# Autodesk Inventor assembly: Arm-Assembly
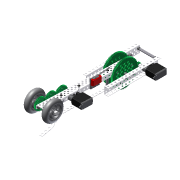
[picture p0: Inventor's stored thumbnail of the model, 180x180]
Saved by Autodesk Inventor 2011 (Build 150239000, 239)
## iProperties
Created: 2007-12
Part Number: Arm-Assembly
Document SubType Name: Assembly
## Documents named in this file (26)
- C:\Data Folder\VEX 2011\Inventor Datasets\Unit 6\Arm-Assembly.iam
- C:\Data Folder\VEX 2011\Inventor Datasets\Unit 6\Components\SCREW-832-0250.ipt
- C:\Data Folder\VEX 2011\Inventor Datasets\Unit 6\Components\BEARING-FLAT.ipt
- C:\Data Folder\VEX 2011\Inventor Datasets\Unit 6\Components\SCREW-832-0375.ipt
- C:\Data Folder\VEX 2011\Inventor Datasets\Unit 6\Components\NUT-832-KEPS.iam
- C:\Data Folder\VEX 2011\Inventor Datasets\Unit 6\Components\SPACER-THICK.ipt
- C:\Data Folder\VEX 2011\Inventor Datasets\Unit 6\Components\SPACER-THIN.ipt
- C:\Data Folder\VEX 2011\Inventor Datasets\Unit 6\Components\SHAFT-COLLAR.iam
- C:\Data Folder\VEX 2011\Inventor Datasets\Unit 6\Components\SHAFT-3000.ipt
- C:\Data Folder\VEX 2011\Inventor Datasets\Unit 6\Components\VEX-36-TOOTH-GEAR.ipt
- C:\Data Folder\VEX 2011\Inventor Datasets\Unit 6\Components\VEX-12-TOOTH-GEAR.ipt
- C:\Data Folder\VEX 2011\Inventor Datasets\Unit 6\Components\VEX-84-TOOTH-GEAR.ipt
- C:\Data Folder\VEX 2011\Inventor Datasets\Unit 6\Components\VL-CHAN-121-25 RevA.ipt
- C:\Data Folder\VEX 2011\Inventor Datasets\Unit 6\Components\SCREW-832-0500.ipt
- C:\Data Folder\VEX 2011\Inventor Datasets\Unit 6\Components\BEARING-RIVET.ipt
- C:\Data Folder\VEX 2011\Inventor Datasets\Unit 6\Components\VEX-MOTOR.iam
- C:\Data Folder\VEX 2011\Inventor Datasets\Unit 6\Components\SCREW-632-0250.ipt
- C:\Data Folder\VEX 2011\Inventor Datasets\Unit 6\Components\SHAFT-2000.ipt
- C:\Data Folder\VEX 2011\Inventor Datasets\Unit 6\Components\LIMIT-SWITCH.iam
- C:\Data Folder\VEX 2011\Inventor Datasets\Unit 6\Components\BEAM-1000.ipt
- C:\Data Folder\VEX 2011\Inventor Datasets\Unit 6\Components\BEAM-2000.ipt
- C:\Data Folder\VEX 2011\Inventor Datasets\Unit 6\Components\VL-CHAN-121-15 RevA.ipt
- C:\Data Folder\VEX 2011\Inventor Datasets\Unit 6\Components\SHAFT-4000.ipt
- C:\Data Folder\VEX 2011\Inventor Datasets\Unit 6\Components\VEX-SMALL-WHEEL.iam
- C:\Data Folder\VEX 2011\Inventor Datasets\Unit 6\Components\VL-BAR-25-bent.ipt
- C:\Data Folder\VEX 2011\Inventor Datasets\Unit 6\Components\SCREW-832-0750.ipt
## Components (92 placed, 25 different names)
1. SPACER-THICK:1 — Mate:159, Mate:161, Mate:162
2. SPACER-THIN:1 — Mate:126, Mate:128
3. VEX-12-TOOTH-GEAR:1 — Mate:163, Mate:164, Angle:7, Mate:279, Rotation:4, Mate:310, Mate:311
4. SCREW-832-0250:5 — Mate:114, Mate:116, Mate:117
5. BEARING-FLAT:3 — Mate:221, Mate:222, Mate:223
6. SPACER-THIN:3 — Mate:123, Mate:132
7. VL-CHAN-121-25 RevA:1 — Mate:105, Mate:106, Mate:107, Mate:108, Mate:110, Angle:1, Mate:111, Mate:112, Mate:201, Mate:210, Mate:211, Mate:212, Flush:7, Mate:214, Flush:8, Mate:215, Mate:216, Mate:217, Mate:218, Mate:219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
8. BEARING-FLAT:8 — Mate:231, Mate:232, Mate:233
9. SHAFT-COLLAR:3 [sub-assembly] — Mate:265, Mate:266
10. BEARING-FLAT:9 — Mate:149, Mate:150, Mate:151, Mate:167
11. BEARING-RIVET:1 — Mate:193, Flush:6, Mate:195
12. BEARING-RIVET:2 — Mate:192, Flush:5, Mate:194
13. BEARING-FLAT:10 — Mate:194, Mate:195, Mate:196, Mate:206
14. BEARING-FLAT:11 — Mate:146, Mate:147, Mate:148, Mate:153
15. VEX-MOTOR:1 [sub-assembly] — Mate:138, Mate:139, Mate:140, Mate:141
16. BEARING-FLAT:12 — Mate:210, Mate:211, Mate:212, Mate:213
17. SCREW-632-0250:1 — Mate:134, Mate:136, Mate:139
18. BEARING-FLAT:13 — Mate:226, Mate:227, Mate:228
19. VEX-12-TOOTH-GEAR:2 — Mate:154, Mate:155, Mate:156, Mate:158, Angle:6
20. VEX-36-TOOTH-GEAR:1 — Mate:256, Mate:257, Mate:264, Angle:19, Angle:23, Angle:24
21. VEX-36-TOOTH-GEAR:2 — Mate:259, Mate:260, Angle:18, Mate:266, Angle:23
22. VEX-36-TOOTH-GEAR:3 — Mate:240, Mate:241, Mate:248, Angle:24
23. VEX-84-TOOTH-GEAR:1 — Mate:168, Angle:10, Mate:176, Mate:177, Mate:178, Mate:179, Mate:182, Mate:183, Mate:201, Mate:287, Mate:288, Mate:290, Insert:1, Insert:2, Mate:309
24. VEX-84-TOOTH-GEAR:2 — Mate:185, Mate:186, Mate:188, Mate:207, Mate:283, Mate:284, Rotation:4, Mate:289, Mate:305
25. BEARING-RIVET:4 — Mate:142, Flush:1, Mate:146
26. SCREW-832-0250:16
27. BEARING-RIVET:5 — Mate:235, Flush:15
28. SCREW-832-0250:17 — Mate:107, Mate:108, Mate:109
29. BEARING-RIVET:7 — Mate:144, Flush:3, Mate:149
30. NUT-832-KEPS:8 [sub-assembly] — Mate:281, Mate:282
31. NUT-832-KEPS:9 [sub-assembly] — Mate:293, Mate:294
32. NUT-832-KEPS:10 [sub-assembly] — Mate:291, Mate:292
33. SCREW-832-0375:6 — Insert:2, Mate:293
34. SCREW-832-0375:7 — Mate:290, Insert:1, Mate:291
35. SHAFT-2000:4 — Mate:258, Mate:259, Angle:17, Mate:261, Mate:262, Angle:18, Mate:265
36. SHAFT-3000:4 — Mate:165, Mate:166, Mate:168, Angle:10, Mate:188, Mate:203, Mate:205, Flush:19, Angle:27
37. SHAFT-3000:5 — Mate:120, Mate:121, Drive this constraint, Mate:141, Mate:152, Mate:154, Mate:155, Mate:157, Mate:159, Mate:160, Mate:163, Angle:6, Angle:7, Angle:25, Angle:27
38. SHAFT-4000:1 — Mate:220, Mate:242, Angle:14, Mate:243, Angle:15, Mate:245, Angle:16, Mate:247, Mate:249, Mate:251, Flush:16
39. SHAFT-COLLAR:6 [sub-assembly] — Mate:263, Mate:264, Angle:20, Flush:17
40. SHAFT-COLLAR:9 [sub-assembly] — Mate:245, Mate:246, Angle:16, Flush:16
41. SHAFT-COLLAR:10 [sub-assembly] — Mate:251, Mate:252
42. SHAFT-2000:3 — Mate:225, Mate:256, Mate:263, Angle:19, Angle:20, Flush:17
43. SHAFT-COLLAR:11 [sub-assembly] — Mate:166, Mate:167, Angle:9, Mate:309
44. NUT-832-KEPS:13 [sub-assembly] — Mate:295, Mate:296
45. BEARING-RIVET:8 — Mate:267, Flush:18
46. BEAM-2000:1 — Mate:299, Mate:300, Mate:301, Mate:303
47. BEARING-RIVET:9 — Flush:11, Mate:224
48. SCREW-832-0250:24 — Mate:301, Mate:302
49. SCREW-832-0500:3 — Mate:274, Mate:276, Mate:298
50. SCREW-832-0500:4 — Mate:269, Angle:22, Mate:297
51. VL-CHAN-121-15 RevA:1 — Mate:121, Mate:122, Mate:123, Mate:132, Mate:142, Mate:143, Mate:144, Mate:145, Flush:1, Flush:2, Flush:3, Flush:4, Mate:148, Mate:151, Mate:165, Angle:9, Angle:11, Angle:12, Flush:19
52. BEARING-RIVET:11 — Mate:143, Flush:2, Mate:147
53. BEARING-RIVET:12 — Mate:145, Flush:4, Mate:150
54. BEARING-FLAT:15 — Mate:215, Mate:216, Mate:217
55. BEARING-RIVET:13 — Mate:213, Flush:7
56. BEARING-RIVET:14 — Mate:214, Flush:8
57. BEARING-RIVET:15 — Mate:229, Flush:12
58. BEARING-RIVET:16 — Mate:219, Flush:10
59. BEARING-RIVET:17 — Mate:230, Flush:13
60. BEARING-RIVET:18 — Mate:234, Flush:14
61. SHAFT-COLLAR:19 [sub-assembly] — Mate:278, Mate:279, Angle:26, Mate:311
62. SCREW-832-0250:38 — Mate:176, Mate:178, Mate:180
63. SCREW-832-0250:39 — Mate:177, Mate:179, Mate:181
64. BEAM-1000:5 — Mate:180, Mate:182, Angle:12
65. BEAM-1000:6 — Mate:181, Mate:183, Angle:11
66. SPACER-THIN:5 — Mate:236, Mate:237, Mate:244
67. SPACER-THIN:6 — Mate:247, Mate:248, Mate:250
68. SPACER-THIN:7 — Mate:160, Mate:162, Mate:164, Mate:310
69. SPACER-THIN:10 — Mate:152, Mate:153, Mate:156
70. LIMIT-SWITCH:2 [sub-assembly] — Angle:28, Mate:285, Mate:286, Mate:297, Mate:298
71. BEAM-2000:2 — Mate:109, Mate:110, Angle:1, Mate:117, Mate:119
72. VEX-MOTOR:3 [sub-assembly] — Mate:253, Mate:254, Mate:255, Angle:17, Mate:261, Mate:262
73. BEAM-2000:3 — Mate:111, Mate:112, Mate:118
74. SCREW-832-0250:41 — Mate:113, Mate:115, Mate:118
75. NUT-832-KEPS:26 [sub-assembly] — Mate:270, Mate:272, Angle:21
76. BEARING-RIVET:21 — Mate:218, Flush:9
77. SCREW-832-0375:12 — Mate:283, Mate:284, Mate:295
78. VEX-SMALL-WHEEL:1 [sub-assembly] — Mate:242, Angle:14, Mate:249, Mate:250, Mate:252
79. VEX-SMALL-WHEEL:2 [sub-assembly] — Mate:243, Angle:15, Mate:244, Mate:246
80. VL-BAR-25-bent:1 — Mate:113, Mate:114, Mate:115, Mate:116, Mate:119, Mate:304
81. SCREW-632-0250:7 — Mate:135, Mate:137, Mate:138
82. SCREW-832-0375:13 — Mate:185, Mate:186, Mate:280, Mate:281
83. SCREW-832-0250:43 — Mate:303, Mate:304
84. BEAM-2000:4 — Mate:208, Mate:209
85. VL-CHAN-121-15 RevA:2 — Mate:120, Drive this constraint, Mate:125, Mate:126, Mate:127, Mate:128, Mate:134, Mate:135, Mate:136, Mate:137, Mate:140, Mate:192, Mate:193, Flush:5, Flush:6, Mate:196, Mate:203
86. SHAFT-COLLAR:21 [sub-assembly] — Mate:157, Mate:158, Mate:161, Angle:25, Mate:278, Angle:26
87. SCREW-832-0250:44
88. NUT-832-KEPS:29 [sub-assembly] — Mate:276, Mate:277
89. SCREW-832-0750:1 — Mate:125, Mate:127, Mate:209
90. SCREW-832-0750:2 — Mate:122, Mate:208
91. SCREW-832-0250:46 — Mate:105, Mate:106
92. SPACER-THICK:2 — Mate:205, Mate:206, Mate:207, Mate:305
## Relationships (220: Mate 175, Angle 23, Flush 19, Insert 2, RelateRotation 1)
- Mate:105: VL-CHAN-121-25 RevA:1 ↔ SCREW-832-0250:46
- Mate:106: VL-CHAN-121-25 RevA:1 ↔ SCREW-832-0250:46
- Mate:107: VL-CHAN-121-25 RevA:1 ↔ SCREW-832-0250:17
- Mate:108: VL-CHAN-121-25 RevA:1 ↔ SCREW-832-0250:17
- Mate:109: SCREW-832-0250:17 ↔ BEAM-2000:2
- Mate:110: VL-CHAN-121-25 RevA:1 ↔ BEAM-2000:2
- Angle:1: VL-CHAN-121-25 RevA:1 ↔ BEAM-2000:2
- Mate:111: VL-CHAN-121-25 RevA:1 ↔ BEAM-2000:3
- Mate:112: VL-CHAN-121-25 RevA:1 ↔ BEAM-2000:3
- Mate:113: SCREW-832-0250:41 ↔ VL-BAR-25-bent:1
- Mate:114: SCREW-832-0250:5 ↔ VL-BAR-25-bent:1
- Mate:115: SCREW-832-0250:41 ↔ VL-BAR-25-bent:1
- Mate:116: SCREW-832-0250:5 ↔ VL-BAR-25-bent:1
- Mate:117: SCREW-832-0250:5 ↔ BEAM-2000:2
- Mate:118: BEAM-2000:3 ↔ SCREW-832-0250:41
- Mate:119: BEAM-2000:2 ↔ VL-BAR-25-bent:1
- Mate:120: SHAFT-3000:5 ↔ VL-CHAN-121-15 RevA:2
- Mate:121: SHAFT-3000:5 ↔ VL-CHAN-121-15 RevA:1
- Drive this constraint [Angle]: SHAFT-3000:5 ↔ VL-CHAN-121-15 RevA:2
- Mate:122: VL-CHAN-121-15 RevA:1 ↔ SCREW-832-0750:2
- Mate:123: SPACER-THIN:3 ↔ VL-CHAN-121-15 RevA:1
- Mate:125: VL-CHAN-121-15 RevA:2 ↔ SCREW-832-0750:1
- Mate:126: SPACER-THIN:1 ↔ VL-CHAN-121-15 RevA:2
- Mate:127: VL-CHAN-121-15 RevA:2 ↔ SCREW-832-0750:1
- Mate:128: SPACER-THIN:1 ↔ VL-CHAN-121-15 RevA:2
- Mate:132: SPACER-THIN:3 ↔ VL-CHAN-121-15 RevA:1
- Mate:134: SCREW-632-0250:1 ↔ VL-CHAN-121-15 RevA:2
- Mate:135: SCREW-632-0250:7 ↔ VL-CHAN-121-15 RevA:2
- Mate:136: SCREW-632-0250:1 ↔ VL-CHAN-121-15 RevA:2
- Mate:137: SCREW-632-0250:7 ↔ VL-CHAN-121-15 RevA:2
- Mate:138: VEX-MOTOR:1 ↔ SCREW-632-0250:7
- Mate:139: VEX-MOTOR:1 ↔ SCREW-632-0250:1
- Mate:140: VEX-MOTOR:1 ↔ VL-CHAN-121-15 RevA:2
- Mate:141: VEX-MOTOR:1 ↔ SHAFT-3000:5
- Mate:142: BEARING-RIVET:4 ↔ VL-CHAN-121-15 RevA:1
- Mate:143: VL-CHAN-121-15 RevA:1 ↔ BEARING-RIVET:11
- Mate:144: BEARING-RIVET:7 ↔ VL-CHAN-121-15 RevA:1
- Mate:145: VL-CHAN-121-15 RevA:1 ↔ BEARING-RIVET:12
- Flush:1: BEARING-RIVET:4 ↔ VL-CHAN-121-15 RevA:1
- Flush:2: VL-CHAN-121-15 RevA:1 ↔ BEARING-RIVET:11
- Flush:3: BEARING-RIVET:7 ↔ VL-CHAN-121-15 RevA:1
- Flush:4: VL-CHAN-121-15 RevA:1 ↔ BEARING-RIVET:12
- Mate:146: BEARING-FLAT:11 ↔ BEARING-RIVET:4
- Mate:147: BEARING-FLAT:11 ↔ BEARING-RIVET:11
- Mate:148: BEARING-FLAT:11 ↔ VL-CHAN-121-15 RevA:1
- Mate:149: BEARING-FLAT:9 ↔ BEARING-RIVET:7
- Mate:150: BEARING-FLAT:9 ↔ BEARING-RIVET:12
- Mate:151: BEARING-FLAT:9 ↔ VL-CHAN-121-15 RevA:1
- Mate:152: SHAFT-3000:5 ↔ SPACER-THIN:10
- Mate:153: BEARING-FLAT:11 ↔ SPACER-THIN:10
- Mate:154: VEX-12-TOOTH-GEAR:2 ↔ SHAFT-3000:5
- Mate:155: VEX-12-TOOTH-GEAR:2 ↔ SHAFT-3000:5
- Mate:156: VEX-12-TOOTH-GEAR:2 ↔ SPACER-THIN:10
- Mate:157: SHAFT-3000:5 ↔ SHAFT-COLLAR:21
- Mate:158: VEX-12-TOOTH-GEAR:2 ↔ SHAFT-COLLAR:21
- Mate:159: SPACER-THICK:1 ↔ SHAFT-3000:5
- Mate:160: SHAFT-3000:5 ↔ SPACER-THIN:7
- Mate:161: SPACER-THICK:1 ↔ SHAFT-COLLAR:21
- Mate:162: SPACER-THICK:1 ↔ SPACER-THIN:7
- Mate:163: VEX-12-TOOTH-GEAR:1 ↔ SHAFT-3000:5
- Mate:164: VEX-12-TOOTH-GEAR:1 ↔ SPACER-THIN:7
- Angle:6: VEX-12-TOOTH-GEAR:2 ↔ SHAFT-3000:5
- Angle:7: VEX-12-TOOTH-GEAR:1 ↔ SHAFT-3000:5
- Mate:165: SHAFT-3000:4 ↔ VL-CHAN-121-15 RevA:1
- Mate:166: SHAFT-3000:4 ↔ SHAFT-COLLAR:11
- Mate:167: BEARING-FLAT:9 ↔ SHAFT-COLLAR:11
- Angle:9: SHAFT-COLLAR:11 ↔ VL-CHAN-121-15 RevA:1
- Mate:168: VEX-84-TOOTH-GEAR:1 ↔ SHAFT-3000:4
- Angle:10: VEX-84-TOOTH-GEAR:1 ↔ SHAFT-3000:4
- Mate:176: VEX-84-TOOTH-GEAR:1 ↔ SCREW-832-0250:38
- Mate:177: VEX-84-TOOTH-GEAR:1 ↔ SCREW-832-0250:39
- Mate:178: VEX-84-TOOTH-GEAR:1 ↔ SCREW-832-0250:38
- Mate:179: VEX-84-TOOTH-GEAR:1 ↔ SCREW-832-0250:39
- Mate:180: SCREW-832-0250:38 ↔ BEAM-1000:5
- Mate:181: SCREW-832-0250:39 ↔ BEAM-1000:6
- Mate:182: VEX-84-TOOTH-GEAR:1 ↔ BEAM-1000:5
- Mate:183: VEX-84-TOOTH-GEAR:1 ↔ BEAM-1000:6
- Angle:11: VL-CHAN-121-15 RevA:1 ↔ BEAM-1000:6
- Angle:12: VL-CHAN-121-15 RevA:1 ↔ BEAM-1000:5
- Mate:185: VEX-84-TOOTH-GEAR:2 ↔ SCREW-832-0375:13
- Mate:186: VEX-84-TOOTH-GEAR:2 ↔ SCREW-832-0375:13
- Mate:188: VEX-84-TOOTH-GEAR:2 ↔ SHAFT-3000:4
- Mate:192: BEARING-RIVET:2 ↔ VL-CHAN-121-15 RevA:2
- Mate:193: BEARING-RIVET:1 ↔ VL-CHAN-121-15 RevA:2
- Flush:5: BEARING-RIVET:2 ↔ VL-CHAN-121-15 RevA:2
- Flush:6: BEARING-RIVET:1 ↔ VL-CHAN-121-15 RevA:2
- Mate:194: BEARING-RIVET:2 ↔ BEARING-FLAT:10
- Mate:195: BEARING-RIVET:1 ↔ BEARING-FLAT:10
- Mate:196: BEARING-FLAT:10 ↔ VL-CHAN-121-15 RevA:2
- Mate:201: VL-CHAN-121-25 RevA:1 ↔ VEX-84-TOOTH-GEAR:1
- Mate:203: SHAFT-3000:4 ↔ VL-CHAN-121-15 RevA:2
- Mate:205: SHAFT-3000:4 ↔ SPACER-THICK:2
- Mate:206: BEARING-FLAT:10 ↔ SPACER-THICK:2
- Mate:207: VEX-84-TOOTH-GEAR:2 ↔ SPACER-THICK:2
- Mate:208: BEAM-2000:4 ↔ SCREW-832-0750:2
- Mate:209: BEAM-2000:4 ↔ SCREW-832-0750:1
- Mate:210: VL-CHAN-121-25 RevA:1 ↔ BEARING-FLAT:12
- Mate:211: VL-CHAN-121-25 RevA:1 ↔ BEARING-FLAT:12
- Mate:212: VL-CHAN-121-25 RevA:1 ↔ BEARING-FLAT:12
- Mate:213: BEARING-FLAT:12 ↔ BEARING-RIVET:13
- Flush:7: VL-CHAN-121-25 RevA:1 ↔ BEARING-RIVET:13
- Mate:214: VL-CHAN-121-25 RevA:1 ↔ BEARING-RIVET:14
- Flush:8: VL-CHAN-121-25 RevA:1 ↔ BEARING-RIVET:14
- Mate:215: VL-CHAN-121-25 RevA:1 ↔ BEARING-FLAT:15
- Mate:216: VL-CHAN-121-25 RevA:1 ↔ BEARING-FLAT:15
- Mate:217: VL-CHAN-121-25 RevA:1 ↔ BEARING-FLAT:15
- Mate:218: VL-CHAN-121-25 RevA:1 ↔ BEARING-RIVET:21
- Mate:219: VL-CHAN-121-25 RevA:1 ↔ BEARING-RIVET:16
- Flush:9: VL-CHAN-121-25 RevA:1 ↔ BEARING-RIVET:21
- Flush:10: VL-CHAN-121-25 RevA:1 ↔ BEARING-RIVET:16
- Mate:220: VL-CHAN-121-25 RevA:1 ↔ SHAFT-4000:1
- Mate:221: BEARING-FLAT:3 ↔ VL-CHAN-121-25 RevA:1
- Mate:222: BEARING-FLAT:3 ↔ VL-CHAN-121-25 RevA:1
- Mate:223: BEARING-FLAT:3 ↔ VL-CHAN-121-25 RevA:1
- Flush:11: VL-CHAN-121-25 RevA:1 ↔ BEARING-RIVET:9
- Mate:224: VL-CHAN-121-25 RevA:1 ↔ BEARING-RIVET:9
- Mate:225: VL-CHAN-121-25 RevA:1 ↔ SHAFT-2000:3
- Mate:226: VL-CHAN-121-25 RevA:1 ↔ BEARING-FLAT:13
- Mate:227: VL-CHAN-121-25 RevA:1 ↔ BEARING-FLAT:13
- Mate:228: VL-CHAN-121-25 RevA:1 ↔ BEARING-FLAT:13
- Mate:229: VL-CHAN-121-25 RevA:1 ↔ BEARING-RIVET:15
- Mate:230: VL-CHAN-121-25 RevA:1 ↔ BEARING-RIVET:17
- Flush:12: VL-CHAN-121-25 RevA:1 ↔ BEARING-RIVET:15
- Flush:13: VL-CHAN-121-25 RevA:1 ↔ BEARING-RIVET:17
- Mate:231: VL-CHAN-121-25 RevA:1 ↔ BEARING-FLAT:8
- Mate:232: VL-CHAN-121-25 RevA:1 ↔ BEARING-FLAT:8
- Mate:233: VL-CHAN-121-25 RevA:1 ↔ BEARING-FLAT:8
- Mate:234: VL-CHAN-121-25 RevA:1 ↔ BEARING-RIVET:18
- Mate:235: VL-CHAN-121-25 RevA:1 ↔ BEARING-RIVET:5
- Flush:14: VL-CHAN-121-25 RevA:1 ↔ BEARING-RIVET:18
- Flush:15: VL-CHAN-121-25 RevA:1 ↔ BEARING-RIVET:5
- Mate:236: VL-CHAN-121-25 RevA:1 ↔ SPACER-THIN:5
- Mate:237: VL-CHAN-121-25 RevA:1 ↔ SPACER-THIN:5
- Mate:240: VL-CHAN-121-25 RevA:1 ↔ VEX-36-TOOTH-GEAR:3
- Mate:241: VL-CHAN-121-25 RevA:1 ↔ VEX-36-TOOTH-GEAR:3
- Mate:242: SHAFT-4000:1 ↔ VEX-SMALL-WHEEL:1
- Angle:14: SHAFT-4000:1 ↔ VEX-SMALL-WHEEL:1
- Mate:243: SHAFT-4000:1 ↔ VEX-SMALL-WHEEL:2
- Angle:15: SHAFT-4000:1 ↔ VEX-SMALL-WHEEL:2
- Mate:244: SPACER-THIN:5 ↔ VEX-SMALL-WHEEL:2
- Mate:245: SHAFT-4000:1 ↔ SHAFT-COLLAR:9
- Mate:246: SHAFT-COLLAR:9 ↔ VEX-SMALL-WHEEL:2
- Angle:16: SHAFT-4000:1 ↔ SHAFT-COLLAR:9
- Mate:247: SHAFT-4000:1 ↔ SPACER-THIN:6
- Mate:248: VEX-36-TOOTH-GEAR:3 ↔ SPACER-THIN:6
- Mate:249: SHAFT-4000:1 ↔ VEX-SMALL-WHEEL:1
- Mate:250: SPACER-THIN:6 ↔ VEX-SMALL-WHEEL:1
- Mate:251: SHAFT-4000:1 ↔ SHAFT-COLLAR:10
- Mate:252: SHAFT-COLLAR:10 ↔ VEX-SMALL-WHEEL:1
- Mate:253: VL-CHAN-121-25 RevA:1 ↔ VEX-MOTOR:3
- Mate:254: VL-CHAN-121-25 RevA:1 ↔ VEX-MOTOR:3
- Mate:255: VL-CHAN-121-25 RevA:1 ↔ VEX-MOTOR:3
- Flush:16: SHAFT-4000:1 ↔ SHAFT-COLLAR:9
- Mate:256: VEX-36-TOOTH-GEAR:1 ↔ SHAFT-2000:3
- Mate:257: VL-CHAN-121-25 RevA:1 ↔ VEX-36-TOOTH-GEAR:1
- Mate:258: VL-CHAN-121-25 RevA:1 ↔ SHAFT-2000:4
- Mate:259: VEX-36-TOOTH-GEAR:2 ↔ SHAFT-2000:4
- Mate:260: VL-CHAN-121-25 RevA:1 ↔ VEX-36-TOOTH-GEAR:2
- Angle:17: SHAFT-2000:4 ↔ VEX-MOTOR:3
- Mate:261: SHAFT-2000:4 ↔ VEX-MOTOR:3
- Mate:262: SHAFT-2000:4 ↔ VEX-MOTOR:3
- Angle:18: VEX-36-TOOTH-GEAR:2 ↔ SHAFT-2000:4
- Mate:263: SHAFT-COLLAR:6 ↔ SHAFT-2000:3
- Mate:264: VEX-36-TOOTH-GEAR:1 ↔ SHAFT-COLLAR:6
- Angle:19: VEX-36-TOOTH-GEAR:1 ↔ SHAFT-2000:3
- Angle:20: SHAFT-COLLAR:6 ↔ SHAFT-2000:3
- Flush:17: SHAFT-COLLAR:6 ↔ SHAFT-2000:3
- Mate:265: SHAFT-COLLAR:3 ↔ SHAFT-2000:4
- Mate:266: SHAFT-COLLAR:3 ↔ VEX-36-TOOTH-GEAR:2
- Mate:267: VL-CHAN-121-25 RevA:1 ↔ BEARING-RIVET:8
- Flush:18: VL-CHAN-121-25 RevA:1 ↔ BEARING-RIVET:8
- Mate:269: VL-CHAN-121-25 RevA:1 ↔ SCREW-832-0500:4
- Mate:270: VL-CHAN-121-25 RevA:1 ↔ NUT-832-KEPS:26
- Mate:272: VL-CHAN-121-25 RevA:1 ↔ NUT-832-KEPS:26
- Angle:21: VL-CHAN-121-25 RevA:1 ↔ NUT-832-KEPS:26
- Mate:274: VL-CHAN-121-25 RevA:1 ↔ SCREW-832-0500:3
- Mate:276: SCREW-832-0500:3 ↔ NUT-832-KEPS:29
- Mate:277: VL-CHAN-121-25 RevA:1 ↔ NUT-832-KEPS:29
- Angle:22: VL-CHAN-121-25 RevA:1 ↔ SCREW-832-0500:4
- Angle:23: VEX-36-TOOTH-GEAR:1 ↔ VEX-36-TOOTH-GEAR:2
- Angle:24: VEX-36-TOOTH-GEAR:1 ↔ VEX-36-TOOTH-GEAR:3
- Angle:25: SHAFT-3000:5 ↔ SHAFT-COLLAR:21
- Mate:278: SHAFT-COLLAR:19 ↔ SHAFT-COLLAR:21
- Mate:279: VEX-12-TOOTH-GEAR:1 ↔ SHAFT-COLLAR:19
- Angle:26: SHAFT-COLLAR:19 ↔ SHAFT-COLLAR:21
- Flush:19: SHAFT-3000:4 ↔ VL-CHAN-121-15 RevA:1
- Mate:280: VL-CHAN-121-25 RevA:1 ↔ SCREW-832-0375:13
- Mate:281: NUT-832-KEPS:8 ↔ SCREW-832-0375:13
- Mate:282: VL-CHAN-121-25 RevA:1 ↔ NUT-832-KEPS:8
- Mate:283: VEX-84-TOOTH-GEAR:2 ↔ SCREW-832-0375:12
- Mate:284: VEX-84-TOOTH-GEAR:2 ↔ SCREW-832-0375:12
- Angle:27: SHAFT-3000:4 ↔ SHAFT-3000:5
- Rotation:4 [RelateRotation]: VEX-12-TOOTH-GEAR:1 ↔ VEX-84-TOOTH-GEAR:2
- Angle:28: VL-CHAN-121-25 RevA:1 ↔ LIMIT-SWITCH:2
- Mate:285: VL-CHAN-121-25 RevA:1 ↔ LIMIT-SWITCH:2
- Mate:286: VL-CHAN-121-25 RevA:1 ↔ LIMIT-SWITCH:2
- Mate:287: VL-CHAN-121-25 RevA:1 ↔ VEX-84-TOOTH-GEAR:1
- Mate:288: VL-CHAN-121-25 RevA:1 ↔ VEX-84-TOOTH-GEAR:1
- Mate:289: VL-CHAN-121-25 RevA:1 ↔ VEX-84-TOOTH-GEAR:2
- Mate:290: VEX-84-TOOTH-GEAR:1 ↔ SCREW-832-0375:7
- Insert:1: VEX-84-TOOTH-GEAR:1 ↔ SCREW-832-0375:7
- Mate:291: NUT-832-KEPS:10 ↔ SCREW-832-0375:7
- Mate:292: VL-CHAN-121-25 RevA:1 ↔ NUT-832-KEPS:10
- Insert:2: VEX-84-TOOTH-GEAR:1 ↔ SCREW-832-0375:6
- Mate:293: NUT-832-KEPS:9 ↔ SCREW-832-0375:6
- Mate:294: VL-CHAN-121-25 RevA:1 ↔ NUT-832-KEPS:9
- Mate:295: NUT-832-KEPS:13 ↔ SCREW-832-0375:12
- Mate:296: VL-CHAN-121-25 RevA:1 ↔ NUT-832-KEPS:13
- Mate:297: SCREW-832-0500:4 ↔ LIMIT-SWITCH:2
- Mate:298: SCREW-832-0500:3 ↔ LIMIT-SWITCH:2
- Mate:299: VL-CHAN-121-25 RevA:1 ↔ BEAM-2000:1
- Mate:300: VL-CHAN-121-25 RevA:1 ↔ BEAM-2000:1
- Mate:301: BEAM-2000:1 ↔ SCREW-832-0250:24
- Mate:302: VL-CHAN-121-25 RevA:1 ↔ SCREW-832-0250:24
- Mate:303: BEAM-2000:1 ↔ SCREW-832-0250:43
- Mate:304: VL-BAR-25-bent:1 ↔ SCREW-832-0250:43
- Mate:305: VEX-84-TOOTH-GEAR:2 ↔ SPACER-THICK:2
- Mate:309: VEX-84-TOOTH-GEAR:1 ↔ SHAFT-COLLAR:11
- Mate:310: VEX-12-TOOTH-GEAR:1 ↔ SPACER-THIN:7
- Mate:311: VEX-12-TOOTH-GEAR:1 ↔ SHAFT-COLLAR:19
